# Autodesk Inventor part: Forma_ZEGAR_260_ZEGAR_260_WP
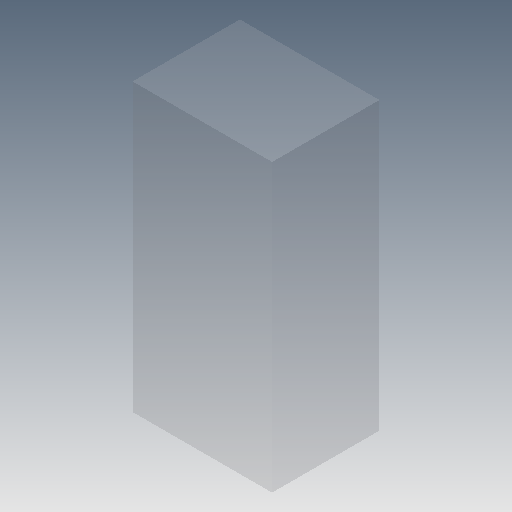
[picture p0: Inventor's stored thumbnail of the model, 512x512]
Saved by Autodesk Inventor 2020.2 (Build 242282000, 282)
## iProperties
Created: 2015-01
Part Number: Forma_ZEGAR_260_ZEGAR_260_WP
Material: Ogólny
Document SubType Name: Modeling
Designer: F.Stasiak
Density: 1 g/cm^3
Appearance: Domyślna
Catalog Web Link: www.expertbooks.pl
Manager: www.cadconsulting.pl
Company: Fabian Stasiak CAD Consulting
Xmin: -39.000 mm
Ymin: -80.000 mm
Zmin: -30.000 mm
Xmax: 39.000 mm
Ymax: 80.000 mm
Zmax: 30.000 mm
d7: -30,000 mm
d8: 39,000 mm
d9: 39,000 mm
d10: 80,000 mm
d11: 80,000 mm
d12: 60,000 mm
d13: 0,00 deg
Author: F.Stasiak
Subject: Zbiór ćwiczeń. Autodesk Inventor 2020. Kurs Professional
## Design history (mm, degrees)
sketch "Szkic2"
  geometry: L1 (-39, 80)-(39, 80); L2 (39, 80)-(39, -80); L3 (39, -80)-(-39, -80); L4 (-39, -80)-(-39, 80); 1 further point
  constraints: 8 end point, 2 parallel, 1 horizontal, 1 perpendicular, 1 other
  dimensions: "d8" = 39 distance from line of L4 point (0, 0) (= -Xmin); "d9" = 39 distance from line of L2 point (0, 0) (= Xmax); "d10" = 80 distance from line of L3 point (0, 0) (= -Ymin); "d11" = 80 distance from line of L1 point (0, 0) (= Ymax)
extrude "Wyciągnięcie proste2" join sketch "Szkic2" distance "d12" = 60 (= Zmax - Zmin); taper "d13" = 0 deg
node "Bryła2"
other parameters: "Xmin" = -39 [user parameter; used in 1 equation term], "Ymin" = -80 [user parameter; used in 1 equation term], "Zmin" = -30 [user parameter; used in 1 equation term], "Xmax" = 39 [user parameter; used in 1 equation term], "Ymax" = 80 [user parameter; used in 1 equation term], "Zmax" = 30 [user parameter; used in 1 equation term], "d7" = -30
